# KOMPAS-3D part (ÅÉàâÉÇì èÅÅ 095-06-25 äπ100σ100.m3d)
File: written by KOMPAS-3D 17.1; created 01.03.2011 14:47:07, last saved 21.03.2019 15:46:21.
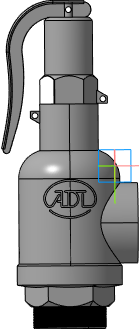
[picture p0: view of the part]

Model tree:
1. Операция без истории:1

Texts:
  Viktor2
